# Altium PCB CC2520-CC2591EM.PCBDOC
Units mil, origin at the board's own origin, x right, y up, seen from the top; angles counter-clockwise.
Board outline 1549 x 1978 mil, 4 copper layers (1, AGND, 3, 4); 56 components, 48 nets, 225 pads, 432 vias.
Unrouted connection lines stored in the file: 5.
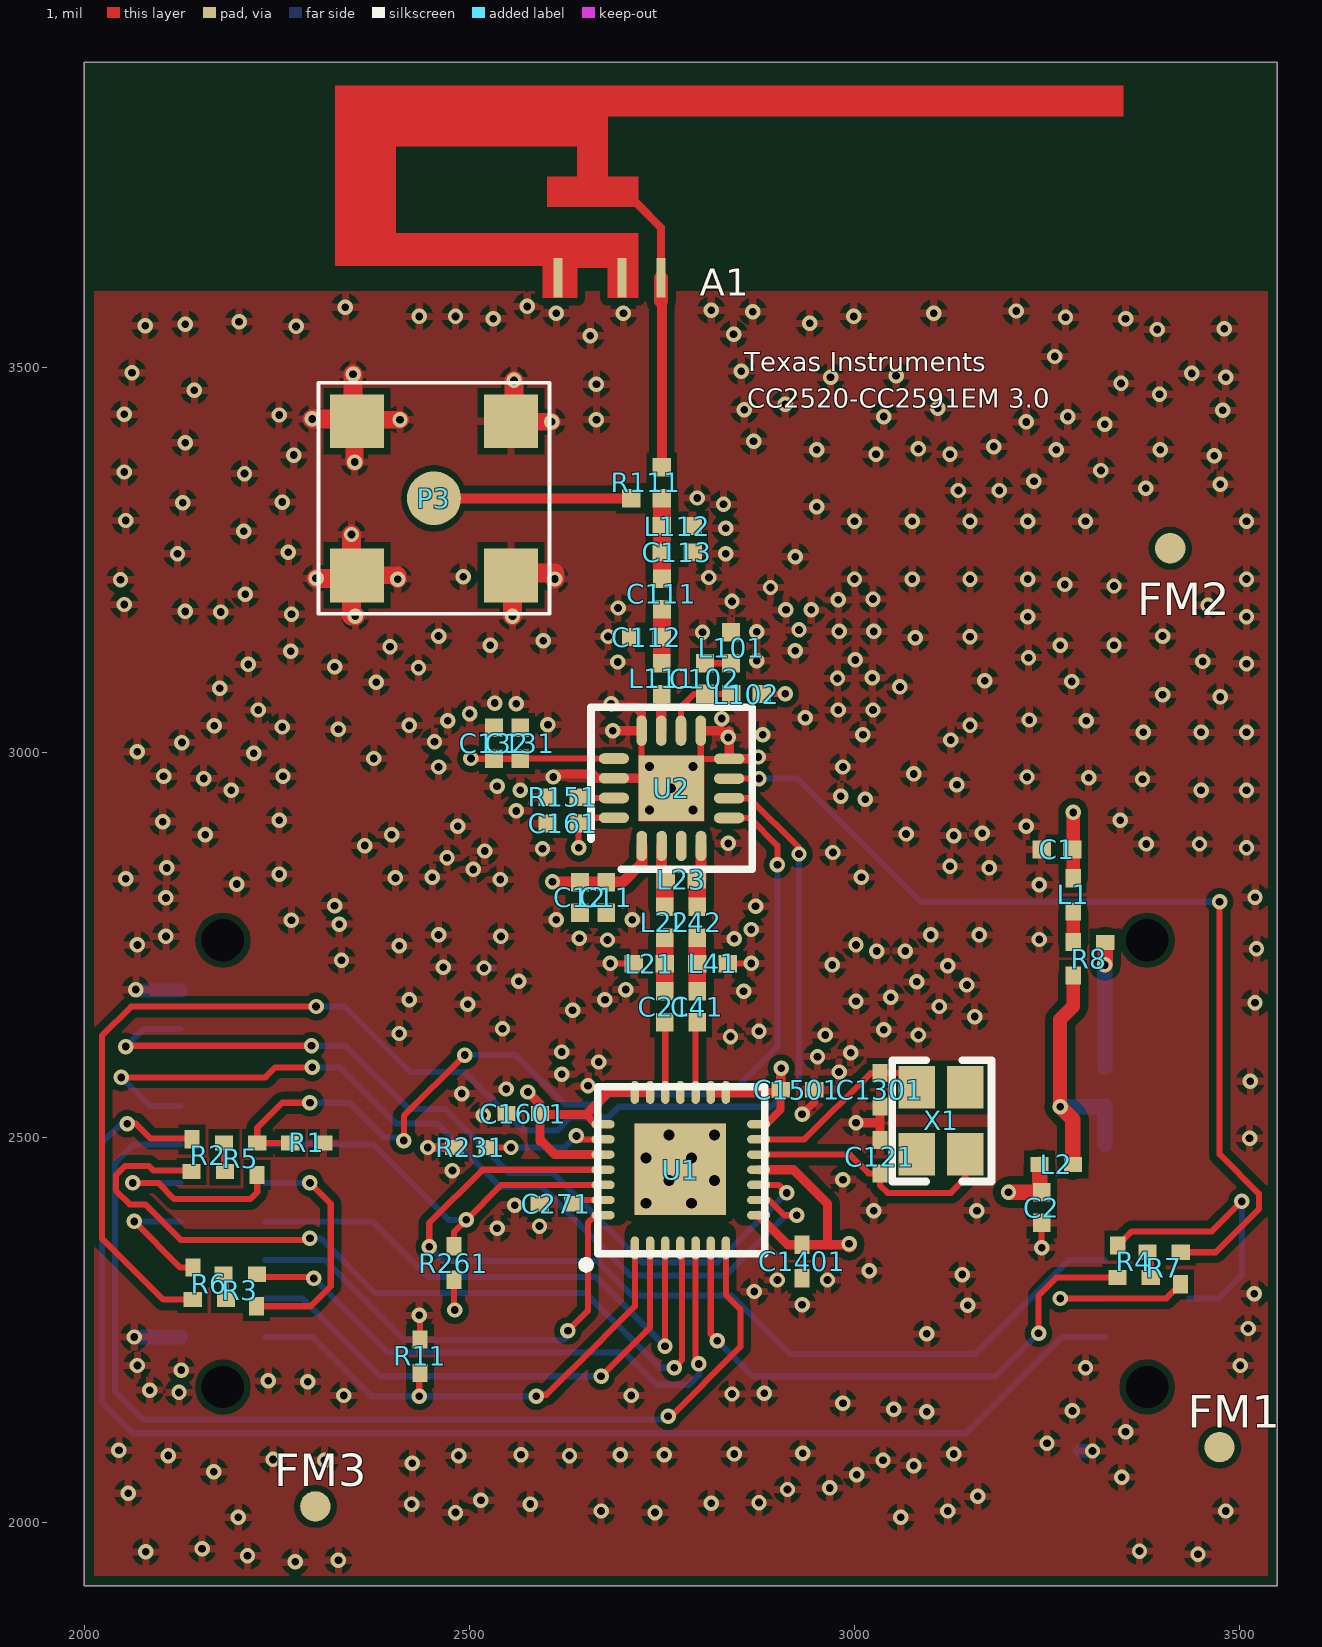
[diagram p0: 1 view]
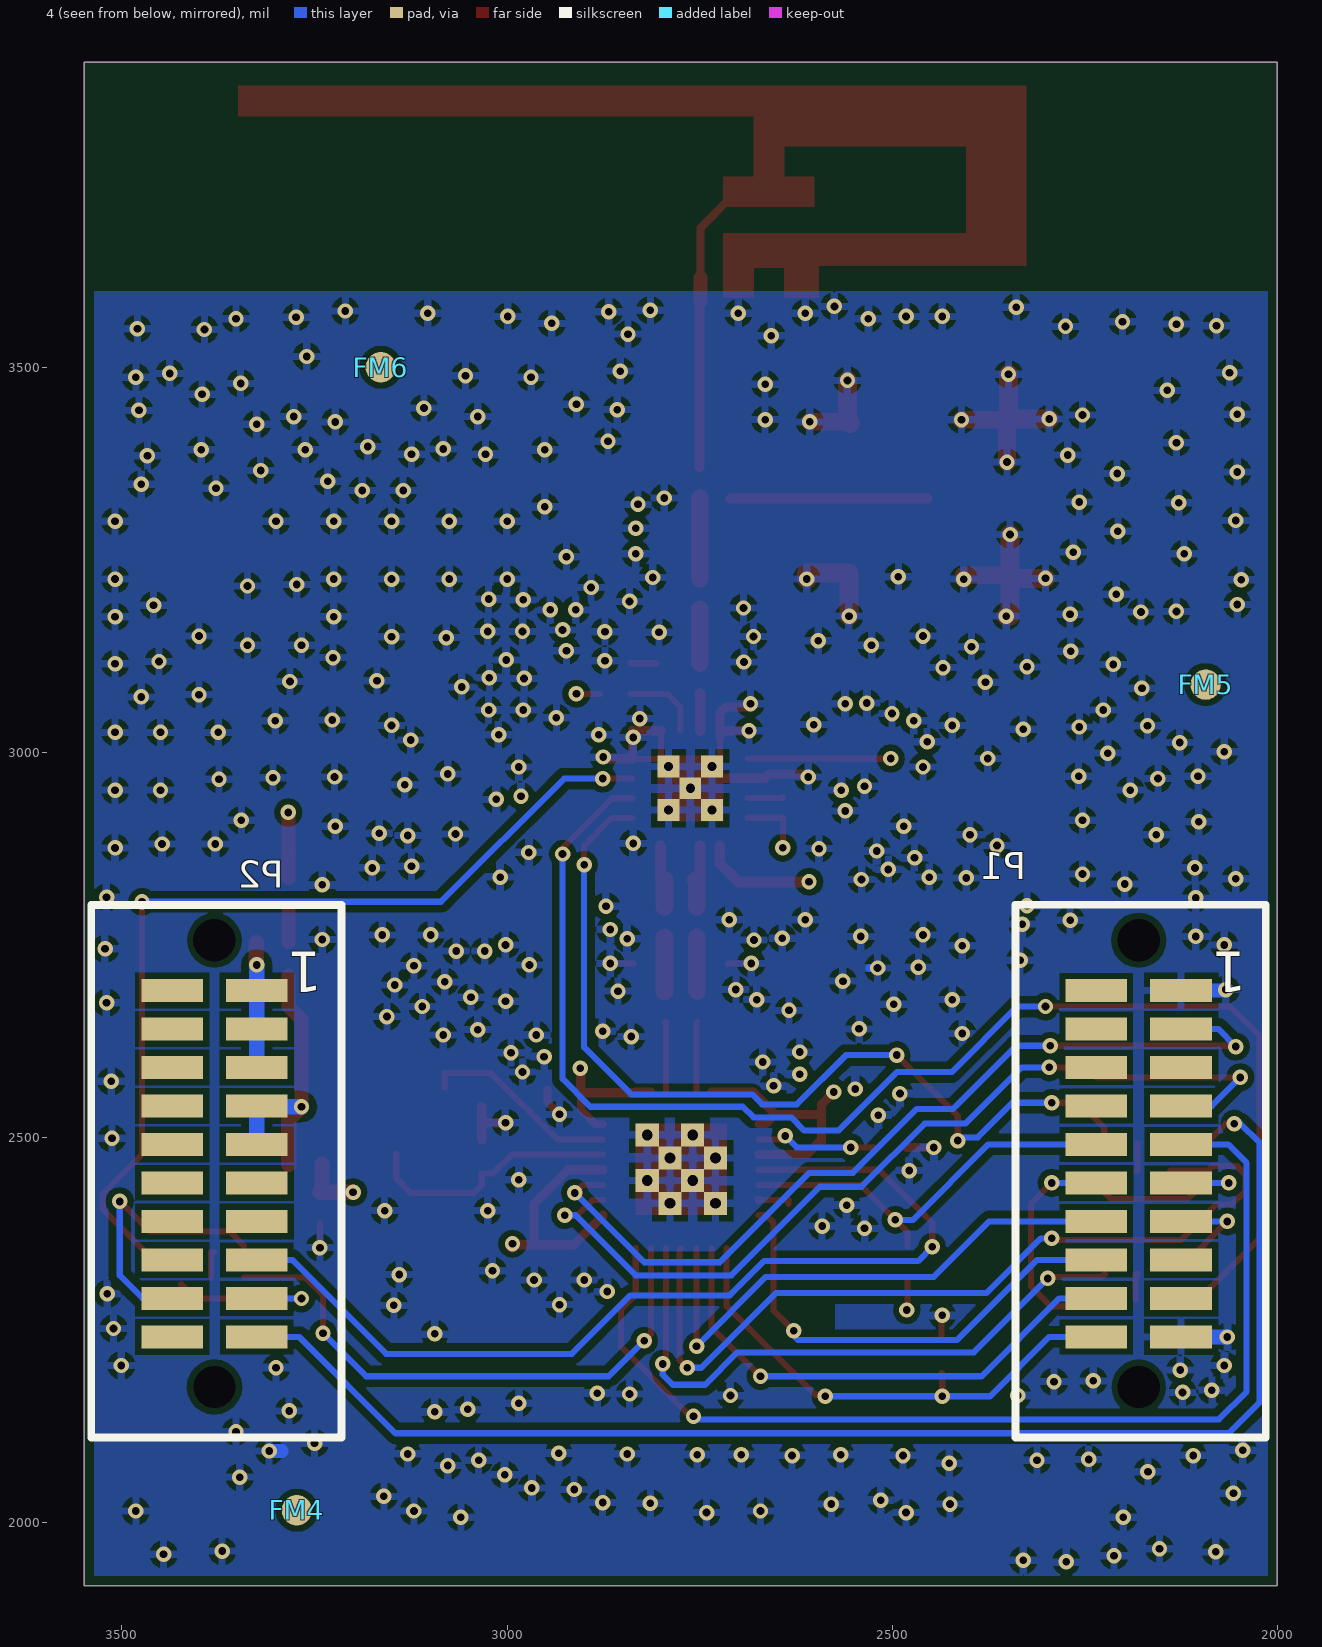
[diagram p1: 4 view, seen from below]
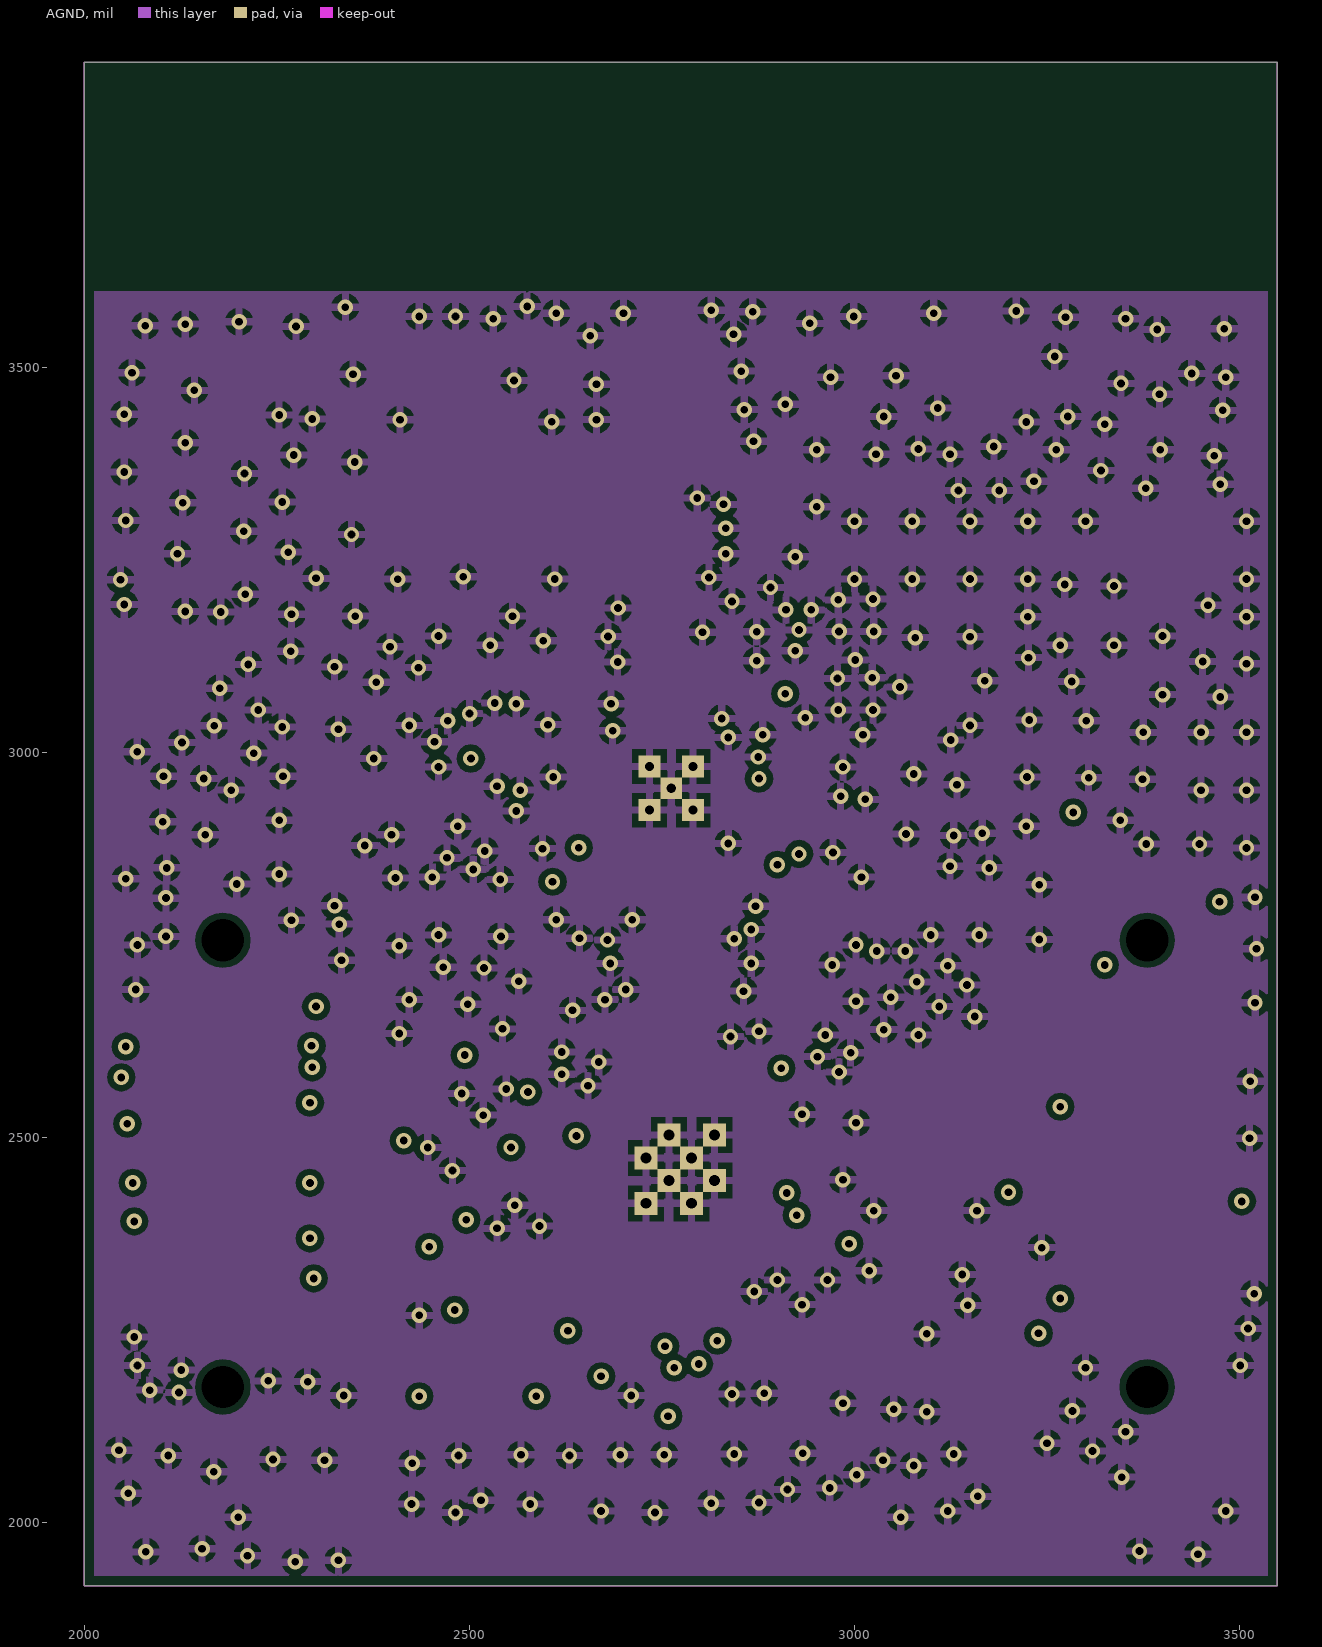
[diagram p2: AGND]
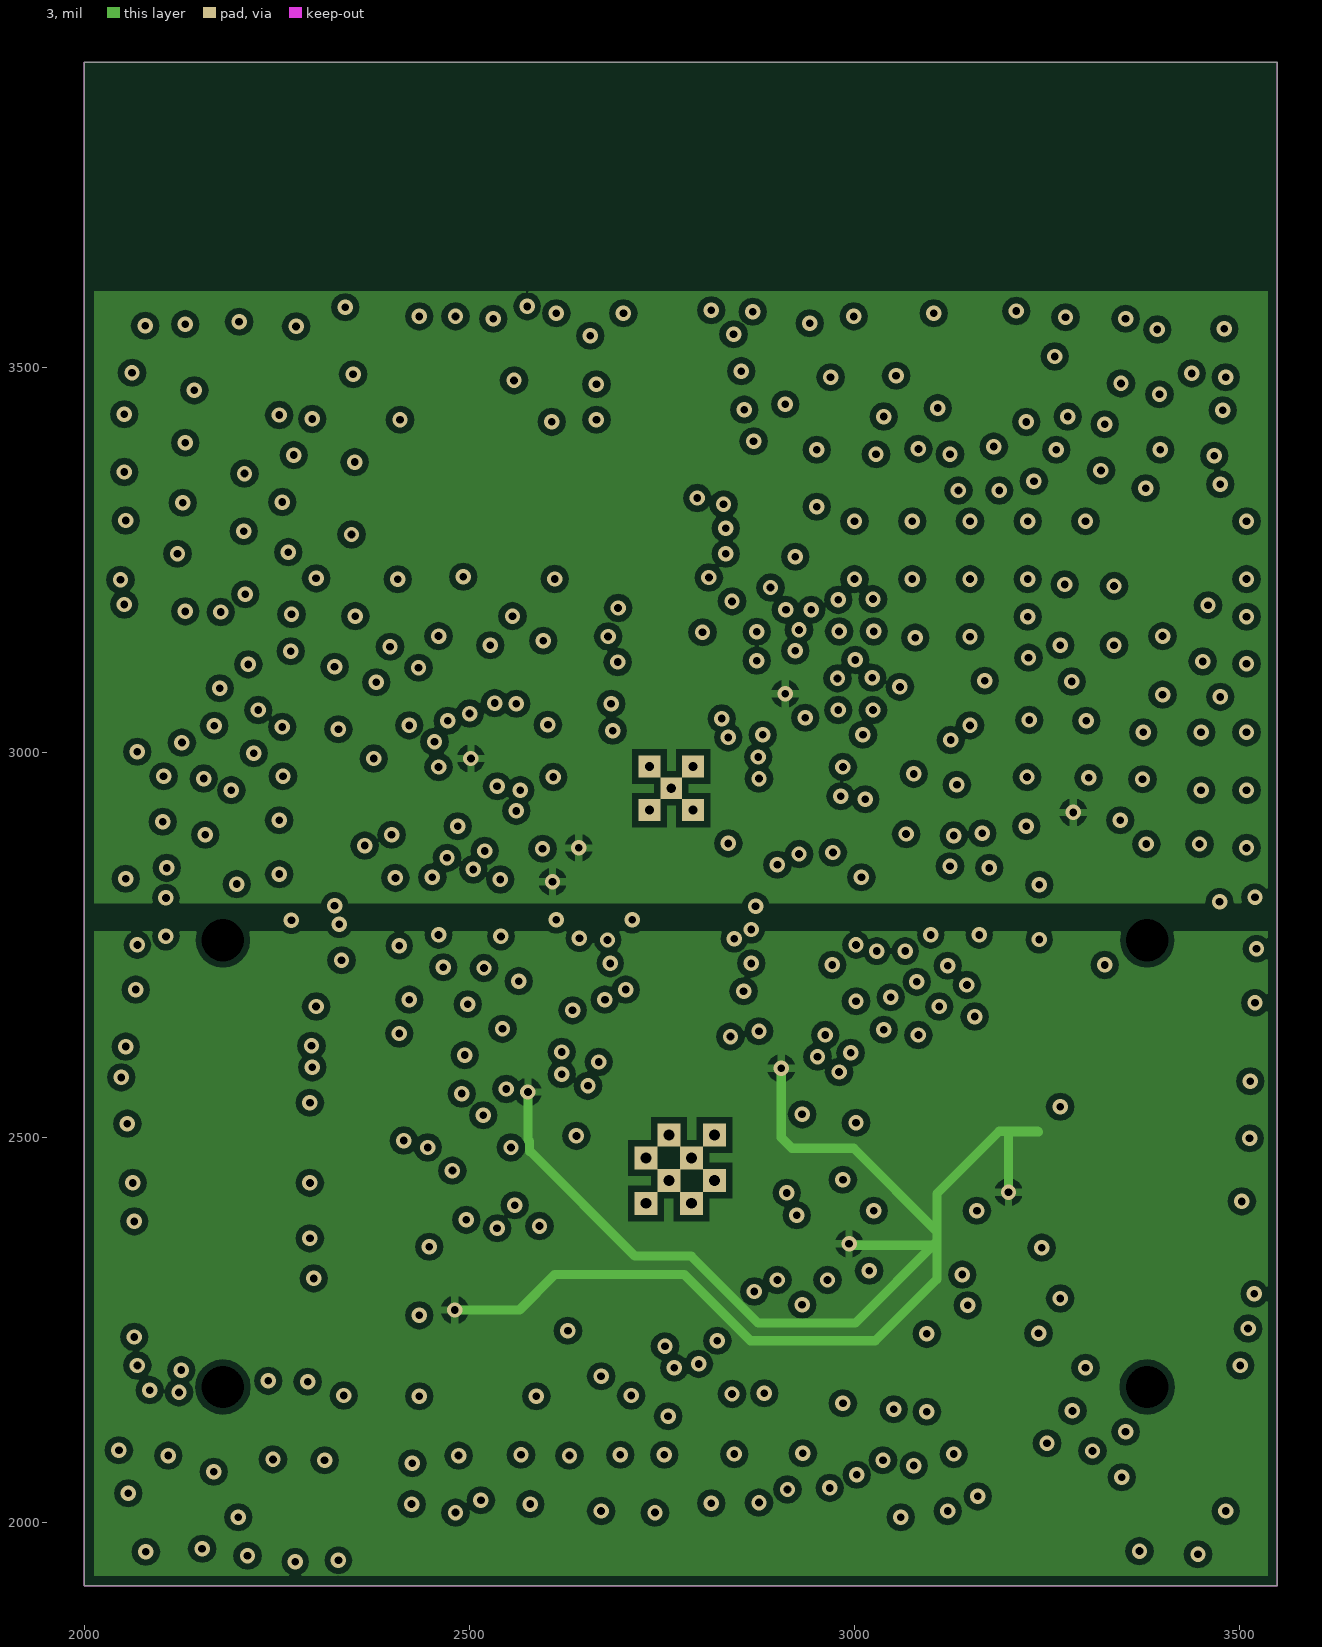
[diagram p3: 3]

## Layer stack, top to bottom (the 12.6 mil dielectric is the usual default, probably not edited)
1: signal copper (thickness not stored)
Dielectric: dielectric 12.6, FR-4, Dk 4.8
AGND: signal copper (thickness not stored)
Dielectric: dielectric 12.6, FR-4, Dk 4.8
3: signal copper (thickness not stored)
Dielectric: dielectric 12.6, FR-4, Dk 4.8
4: signal copper (thickness not stored)

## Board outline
2000,1918 3549,1918 3549,3896 2000,3896

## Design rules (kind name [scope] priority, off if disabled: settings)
Clearance InPolygon_VDD_CC2520_L3_2 [InNamedPolygon('VDD_CC2520_L3_2') vs InNet('VDD_CC2520')] p1: gap=8
Clearance InPolygon_AGND_L1_2 [InNamedPolygon('AGND_L1_2') vs InNet('AGND')] p2: gap=8
Clearance InPolygon_AGND_L4_6 [InNamedPolygon('AGND_L4_6') vs InNet('AGND')] p3: gap=8
Clearance InPolygon_AGND_L4_4 [InNamedPolygon('AGND_L4_4') vs InNet('AGND')] p4: gap=8
Clearance InPolygon_AGND_L2_2 [InNamedPolygon('AGND_L2_2') vs InNet('AGND')] p5: gap=8
Clearance InPolygon_AGND_L4_5 [InNamedPolygon('AGND_L4_5') vs InNet('AGND')] p6: gap=8
Clearance InPolygon_AGND_L4_1 [InNamedPolygon('AGND_L4_1') vs InNet('AGND')] p7: gap=8
Clearance InPolygon_AGND_L4_3 [InNamedPolygon('AGND_L4_3') vs InNet('AGND')] p8: gap=8
Clearance InPolygon_AGND_L2_1 [InNamedPolygon('AGND_L2_1') vs InNet('AGND')] p9: gap=8
Clearance InPolygon_AGND_L4_2 [InNamedPolygon('AGND_L4_2') vs InNet('AGND')] p10: gap=8
Clearance InPolygon_VDD_CC2590_L3_1 [InNamedPolygon('VDD_CC2590_L3_1') vs InNet('VDD_CC2591')] p11: gap=8
Clearance InPolygon_AGND_L1_1 [InNamedPolygon('AGND_L1_1') vs InNet('AGND')] p12: gap=8
Clearance CopperToBoard [InPolygon vs (IsTrack Or IsArc) And OnLayer('Keep-out Layer')] p13: gap=12
Clearance ViaToCopper [IsVia vs InPolygon] p14: gap=8
Clearance ViaToVia [IsVia vs IsVia] p15: gap=8
Clearance PadToCopper [IsPad vs InPolygon] p16: gap=8
Clearance PadToVia [IsPad vs IsVia] p17: gap=8
Clearance PadToPad [IsPad vs IsPad] p18: gap=8
Clearance RouteToPad_1 [IsTrack or IsArc vs IsVia] p19: gap=8
Clearance RouteToPad [IsTrack Or IsArc vs IsPad] p20: gap=8
Clearance RouteToRoute [IsTrack or IsArc vs IsTrack or IsArc] p21: gap=8
Clearance [All] p22: gap=10
PolygonConnect [All] p1: connectstyle=Relief reliefconductorwidth=10 reliefentries=4 polygonreliefangle="90 Angle"
RoutingVias [All] p1: holewidth=28 width=50 viastyle="Through Hole" minholewidth=28 minwidth=50 maxholewidth=28 maxwidth=50
SilkscreenOverComponentPads [All] p1: minsilkscreentomaskgap=10
SolderMaskExpansion [All] p1: expansion=4
Width [All] p1: maxlimit=10 minlimit=10 preferedwidth=10
27 further rules are at their usual default settings.

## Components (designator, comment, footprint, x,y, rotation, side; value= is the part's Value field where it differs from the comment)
A1 "Comment" antenna_IIFA_cc2420 2799,3593 r0 top
C1 "Comment" "0402 (REFLOW LF)" 3263,2874 r180 top
C2 "Comment" "0402 (REFLOW LF)" 3243,2409 r270 top
C11 "Comment" "0402 (REFLOW LF)" 2677.8,2811.6 r270 top
C12 "Comment" "0402 (REFLOW LF)" 2643.7,2811.6 r270 top
C21 "Comment" "0402 (REFLOW LF)" 2753.5,2669.7 r90 top
C41 "Comment" "0402 (REFLOW LF)" 2795.7,2669.6 r90 top
C102 "Comment" "0402 (REFLOW LF)" 2805.8,3095.8 r90 top
C111 "Comment" "0402 (REFLOW LF)" 2750,3205.7 r90 top
C112 "Comment" "0402 (REFLOW LF)" 2730,3149.7 r180 top
C113 "Comment" "0402 (REFLOW LF)" 2770,3259.8 r180 top
C121 "Comment" "0402 (REFLOW)" 3033,2475 r90 top
C131 "Comment" "0402 (REFLOW LF)" 2566,3011.7 r90 top
C132 "Comment" "0402 (REFLOW LF)" 2532,3011.7 r90 top
C161 "Comment" "0402 (REFLOW LF)" 2621.8,2907.7 r180 top
C271 "Comment" "0402 (REFLOW)" 2613,2414 r180 top
C1301 "Comment" "0402 (REFLOW)" 3033,2562 r270 top
C1401 "Comment" "0402 (REFLOW)" 2932,2339 r270 top
C1501 "Comment" "0402 (REFLOW)" 2926,2562 r0 top
C1601 "Comment" "0402 (REFLOW)" 2570,2531 r180 top
FM1 "Comment" FIDUCAL_MARK_1mm 3474,2098 r0 top
FM2 "Comment" FIDUCAL_MARK_1mm 3410,3265 r90 top
FM3 "Comment" FIDUCAL_MARK_1mm 2300,2021 r0 top
FM4 "Comment" FIDUCAL_MARK_1mm 3273,2016 r180 bottom
FM5 "Comment" FIDUCAL_MARK_1mm 2093,3088 r180 bottom
FM6 "Comment" FIDUCAL_MARK_1mm 3164,3500 r180 bottom
L1 "Comment" "0402 (REFLOW)" 3284,2815 r270 top
L2 "Comment" "0402 (REFLOW)" 3262,2465 r0 top
L21 "Comment" "0402 (REFLOW LF)" 2733.7,2725.6 r180 top
L22 "Comment" "0402 (REFLOW LF)" 2753.7,2779.5 r90 top
L23 "Comment" "0402 (REFLOW LF)" 2775,2834.6 r0 top
L41 "Comment" "0402 (REFLOW LF)" 2815.7,2725.6 r0 top
L42 "Comment" "0402 (REFLOW LF)" 2795.7,2779.6 r90 top
L101 "Comment" "0402 (REFLOW LF)" 2839.8,3135.8 r90 top
L102 "Comment" "0402 (REFLOW LF)" 2859.75,3075.75 r180 top
L111 "Comment" "0402 (REFLOW LF)" 2749.75,3095.75 r90 top
L112 "Comment" "0402 (REFLOW LF)" 2770,3293.8 r180 top
P1 "Comment" "SFM SMD Socket 2x10" 2125,2691 r0 bottom
P2 "Comment" "SFM SMD Socket 2x10" 3325,2690.95 r0 bottom
P3 "Comment" "SMA_SMD (Straight)" 2454,3329.9 r0 top
R1 "Comment" "0402 (REFLOW)" 2289,2493 r180 top
R2 "Comment" "0402_3port_1-2 (REFLOW)" 2161,2456 r180 top
R3 "Comment" "0402_3port_1-2 (REFLOW)" 2202.5,2322.5 r0 top
R4 "Comment" "0402_3port_1-2 (REFLOW)" 3363,2318 r180 top
R5 "Comment" "0402_3port_1-2 (REFLOW)" 2203,2493 r0 top
R6 "Comment" "0402_3port_1-2 (REFLOW)" 2162.5,2289.5 r180 top
R7 "Comment" "0402_3port_1-2 (REFLOW)" 3402,2351 r0 top
R8 "Comment" "0402_3port_1-2 (REFLOW)" 3284,2732 r90 top
R11 "Comment" "0402 (REFLOW)" 2436,2216 r90 top
R111 "Comment" "0402_3port_2-3 (REFLOW LF)" 2729.8,3329.8 r270 top
R151 "Comment" "0402 (REFLOW LF)" 2621.8,2941.7 r0 top
R231 "Comment" "0402 (REFLOW)" 2502,2487 r0 top
R261 "Comment" "0402 (REFLOW)" 2480,2337 r270 top
U1 "Comment" "QLP28 (Reflow)" 2774,2457 r90 top
U2 "Comment" "QFN16_4_4_DATASHEET (CC2591)" 2759,2966 r90 top
X1 "Comment" "XTAL_SMD_3_2x2_5 (3.2 x 2.5 mm)" 3081,2565 r270 top

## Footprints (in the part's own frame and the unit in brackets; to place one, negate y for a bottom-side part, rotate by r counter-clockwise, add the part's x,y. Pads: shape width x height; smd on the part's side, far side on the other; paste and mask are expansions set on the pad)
"0402 (REFLOW LF)" [mil]
  rect 24x23 smd paste+0 mask+6: 1(-20,0) 2(20,0)
"0402 (REFLOW)" [mm]
  rect 0.6x0.5 smd paste+0 mask+0.1: 1(-0.55,0) 2(0.55,0)
"0402_3port_1-2 (REFLOW)" [mm]
  rect 0.6x0.5 smd paste+0 mask+0.1: 1(-0.55,0) 2(0.55,0)
  rect 0.5x0.6 smd paste+0 mask+0.1: 3(0.537,-1.057)
"0402_3port_2-3 (REFLOW LF)" [mil]
  rect 24x24 smd paste+0 mask+6: 1(-40.1,20.1) 2(-0.1,20.1) 3(-0.1,-19.9)
antenna_IIFA_cc2420 [mm]
  rect 0.3x1.3 smd paste-0.3 mask-0.3: 1(-1.27,0.584) 2(-2.565,0.584) 3(-4.674,0.584)
  1 region: -1.397,2.134 -1.422,2.21 -2.261,3.048 -2.032,3.175 -1.143,2.286 -1.143,2.134
  1 region: -1.143,-0.076 -1.397,-0.076 -1.397,2.147 -1.143,2.147
  1 region: -2.03,-0.076 -3.03,-0.076 -3.03,0.924 -4.03,0.924 -4.03,-0.076 -5.18,-0.076 -5.18,0.991 -12.012,0.991 -12.012,6.924 13.97,6.924 13.97,5.924 -3.03,5.924 -3.03,3.924 -2.03,3.924 -2.03,2.924 -5.03,2.924 -5.03,3.924 -4.03,3.924 -4.03,4.924 -10.03,4.924 -10.03,2.057 -2.03,2.057
FIDUCAL_MARK_1mm [mil]
  round 39.4 smd paste+0 mask+39.4: 1(0,0)
"QFN16_4_4_DATASHEET (CC2591)" [mm]
  oval 1x0.35 smd paste+0.001 mask+0.14: 1(-2.22,0.89) 2(-2.22,0.24) 3(-2.22,-0.41) 4(-2.22,-1.06) 9(1.58,-1.05) 10(1.58,-0.4) 11(1.58,0.25) 12(1.58,0.9)
  oval 0.35x1 smd paste+0.001 mask+0.14: 5(-1.3,-1.99) 6(-0.65,-1.99) 7(0,-1.99) 8(0.65,-1.99) 13(0.66,1.81) 14(0.01,1.81) 15(-0.64,1.81) 16(-1.29,1.81)
  rect 0.72x0.72 hole 0.3 paste+0 mask+0.14: 17(-1.04,0.64) 19(0.4,0.64) 21(-0.32,-0.08) 23(-1.04,-0.8) 25(0.4,-0.8)
  rect 0.72x0.72 smd paste-0.72 mask+0.14: 18(-0.32,0.64) 20(-1.04,-0.08) 22(0.4,-0.08) 24(-0.32,-0.8)
  1 region: -1.4,-1.16 0.76,-1.16 0.76,1 -1.4,1
  1 region: -1.4,-1.16 0.76,-1.16 0.76,1 -1.4,1
  1 region: -1.4,-1.16 0.76,-1.16 0.76,1 -1.4,1
  1 region: -1.4,-1.16 0.76,-1.16 0.76,1 -1.4,1
  1 region: -1.4,-1.16 0.76,-1.16 0.76,1 -1.4,1
  1 region: -1.4,-1.16 0.76,-1.16 0.76,1 -1.4,1
  1 region: -1.4,-1.16 0.76,-1.16 0.76,1 -1.4,1
  1 region: -1.4,-1.16 0.76,-1.16 0.76,1 -1.4,1
  silkscreen extent -2.99,-2.75 2.35,2.57
"QLP28 (Reflow)" [mil]
  oval 30x11 smd paste+0 mask+2: 1(-100.39,59.06) 2(-100.39,39.37) 3(-100.39,19.68) 4(-100.39,0) 5(-100.39,-19.69) 6(-100.39,-39.37) 7(-100.39,-59.06) 15(101.57,-59.06) 16(101.57,-39.37) 17(101.57,-19.69) 18(101.57,0) 19(101.57,19.68) 20(101.57,39.37) 21(101.57,59.06)
  oval 11x30 smd paste+0 mask+2: 8(-57.87,-101.57) 9(-38.19,-101.57) 10(-18.5,-101.57) 11(1.18,-101.57) 12(20.87,-101.57) 13(40.55,-101.57) 14(60.24,-101.57) 22(60.24,100.39) 23(40.55,100.39) 24(20.87,100.39) 25(1.18,100.39) 26(-18.5,100.39) 27(-38.19,100.39) 28(-57.87,100.39)
  rect 30x30 hole 14 paste+0 mask+0: 29(-42.52,44.49) 31(16.54,44.49) 34(-12.99,14.96) 36(46.06,14.96) 37(-42.52,-14.57) 39(16.54,-14.57) 42(-12.99,-44.09) 44(46.06,-44.09)
  rect 30x30 smd mask+0: 30(-12.99,44.49) 32(46.06,44.49) 33(-42.52,14.96) 35(16.54,14.96) 38(-12.99,-14.57) 40(46.06,-14.57) 41(-42.52,-44.09) 43(16.54,-44.09)
  1 region: -55.51,57.48 59.06,57.48 59.06,-57.09 -55.51,-57.09
  1 region: -55.51,57.48 59.06,57.48 59.06,-57.09 -55.51,-57.09
  1 region: -55.51,57.48 59.06,57.48 59.06,-57.09 -55.51,-57.09
  1 region: -55.51,57.48 59.06,57.48 59.06,-57.09 -55.51,-57.09
  1 region: -55.51,57.48 59.06,57.48 59.06,-57.09 -55.51,-57.09
  1 region: -55.51,57.48 59.06,57.48 59.06,-57.09 -55.51,-57.09
  1 region: -55.51,57.48 59.06,57.48 59.06,-57.09 -55.51,-57.09
  1 region: -55.51,57.48 59.06,57.48 59.06,-57.09 -55.51,-57.09
  1 region: -55.51,57.48 59.06,57.48 59.06,-57.09 -55.51,-57.09
  1 region: -55.51,57.48 59.06,57.48 59.06,-57.09 -55.51,-57.09
  1 region: -57.48,59.45 61.02,59.45 61.02,-59.06 -57.48,-59.06
  1 region: -55.51,57.48 59.06,57.48 59.06,-57.09 -55.51,-57.09
  1 region: -55.51,57.48 59.06,57.48 59.06,-57.09 -55.51,-57.09
  1 region: -55.51,57.48 59.06,57.48 59.06,-57.09 -55.51,-57.09
  1 region: -55.51,57.48 59.06,57.48 59.06,-57.09 -55.51,-57.09
  silkscreen extent -132,-109 109,132
"SFM SMD Socket 2x10" [mil]
  rect 80x30 smd paste-2 mask+4: 1(0,0) 2(110,0) 3(0,50) 4(110,50) 5(0,100) 6(110,100) 7(0,150) 8(110,150) 9(0,200) 10(110,200) 11(0,250) 12(110,250) 13(0,300) 14(110,300) 15(0,350) 16(110,350) 17(0,400) 18(110,400) 19(0,450) 20(110,450)
  round 5 hole 55 paste+0 mask+55: 21(55,-65) 22(54.96,515)
  silkscreen extent -110,-111 215,581
"SMA_SMD (Straight)" [mil]
  round 70 smd paste+0 mask+3: 1(0,0)
  rect 70x70 smd paste+0 mask+3: 2(-100,100) 3(-100,-100) 4(100,-100) 5(100,100)
  silkscreen extent -150,-150 150,150
"XTAL_SMD_3_2x2_5 (3.2 x 2.5 mm)" [mm]
  rect 1.4x1.2 smd paste-0.001 mask+0.05: 1(0,0) 2(2.2,0) 3(2.2,1.6) 4(0,1.6)
  silkscreen extent -0.9,-0.81 3.1,2.46

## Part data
A1: library part Antenna_IIFA_cc2420, "Antenna single ended IIFA, CC2420"
C1 C2: library part C_2U2_0402_X5R_M_4VDC, "Capasitor 0402, GRM155R60G225ME15J"
C11 C131 C161: library part C_1N_0402_NP0_J_50, "Capacitor 0402"
C12 C132: library part C_0402, "Capacitor 0402, general"
C21: library part C_3P0_0402_NP0_C_50, "Capacitor 0603"
C41: library part C_3P9_0402_NP0_C_50, "Capacitor 0402"
C102: library part L_1N1_0402_S, "Inductor, 1n1, 0402, LQG15HS1N1S02D"
C111: library part C_6P8_0402_NP0_C_50, "Capacitor 0402"
C112: library part C_1P0_0402_NP0_B_50, "Capacitor, 1p, 0402, NP0, +/-0.1pF 50V"
C113: library part C_2P7_0402_NP0_C_50, "Capacitor 0402"
C121 C1301: library part C_27P_0402_NP0_J_50, "Capacitor 0402"
C271 C1401 C1501 C1601: library part C_100N_0402_X5R_K_10, "Capacitor 0402"
FM1 FM2 FM3 FM4 FM5 FM6: library part FIDUCIAL_MARK_1MM, "Fiducial mark, 1mm metal diameter"
L1 L2: library part L_BEAD_102_0402, "EMI filter bead"
L21 L41 L42 L112: library part L_1N0_0402_S, "Inductor 0402"
L22: library part L_2N0_0402_S, "Inductor 0402"
L23: library part L_0402, "Inductor 0402, general"
L101: library part C_15P_0402_NP0_J_50, "Capacitor, 0402"
L102: library part L_5N1_0402_J, "Inductor 0402"
L111: library part L_1N5_0402_B_LQW, "Inductor, 1n5, 0402, Wire-wound type, +/-0.1 nH"
P1 P2: library part SMD_SOCKET_2x10, "SMD pinrow socket, .050 spacing, SFM-110-02-SM-D-A-K-TR"
P3: library part SMA_SMD, "Surface-mount SMA, straight"
R1: library part R_330K_0402_F, "Resistor 0402"
R2 R3 R4 R5 R6 R7 R8: library part R_0_0402_3PORT_1-2, "0402 3-port footprint, default connection 1-2"
R11: library part R_1M0_0402_F, "Resistor 0402"
R111: library part R_0_0402_3PORT_2-3, "0402 3-port footprint, default connection 2-3"
R151: library part R_4K3_0402_G, "Resistor 0402"
R231: library part R_56K_0402_F, "Resistor 0402"
R261: library part R_0402, "Resistor 0402, general"
U1: library part CC2520, "Single-chip transceiver"
U2: library part CC2591_DATASHEET, "CC2591 w/ datasheet footprint"
X1: library part X_32.000/10/15/30/16, "Crystal, ceramic SMD 3.2x2.5mm"

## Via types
v1: diameter 20, hole 10, 1 to 4, 432 vias

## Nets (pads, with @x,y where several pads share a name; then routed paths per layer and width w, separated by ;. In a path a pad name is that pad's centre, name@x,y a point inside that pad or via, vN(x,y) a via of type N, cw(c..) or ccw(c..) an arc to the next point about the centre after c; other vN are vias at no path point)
276: C1301.1 U1.13 X1.1 | length 270.7
  1 w8: U1.13 2934.9,2497.55 3021,2583.65 C1301.1 ; C1301.1 C1301.1@3038,2583.65 ; C1301.1 C1301.1@3038,2583.65 ; C1301.1@3038,2583.65 3081,2583.65 X1.1@3081,2571 ; X1.1@3081,2571 X1.1 X1.1@3081,2571
528: P2.15 U1.25 | length 1395.8
  1 w8: v1(2448,2358) 2448,2389 2517.18,2458.18 2548.18,2458.18 ; 2548.18,2458.18 U1.25 2548.18,2458.18
  4 w8: v1(2448,2358) 2466.5,2339.5 2666.5,2339.5 2711,2295 2840,2295 2916,2219 3157.05,2219 3279,2340.95 P2.15
536: R231.2 U1.23 | length 160.6
  1 w8: R231.2 v1(2554,2487) ; v1(2639,2502) 2639,2497.55 U1.23
  4 w8: v1(2554,2487) 2624,2487 v1(2639,2502)
571: C271.1 U1.27 | length 83.1
  1 w8: C271.1 2634.65,2418.81 U1.27 2673.61,2419 C271.1@2634.65,2419
  1 w10: U1.27 U1.27@2673.61,2419
574: P1.10 R261.1 U1.26 | length 548.5
  1 w8: R261.1 2480,2377 v1@2495,2392 ; v1(2496,2393) v1@2495,2392 ; U1.26@2665.5,2438.5 U1.26 2541.5,2438.5 v1@2495,2392
  4 w8: P1.10 2375,2491 2473,2393 v1(2496,2393)
576: P1.20 R11.1 U1.1 | length 676
  1 w8: v1(2435,2164) 2435,2193.5 R11.1 ; v1(2587,2164) 2587,2166 2600,2166 2629,2195 ; U1.1 2714.94,2280.94 2634,2200 ; 2629,2195 2634,2200 ; 2629,2195 2634,2200
  4 w8: P1.20 2296,2241 2373,2164 v1@2436,2164 ; v1(2435,2164) v1@2436,2164 ; v1(2587,2164) v1@2436,2164
577: P1.18 U1.2 | length 672
  1 w8: v1(2671,2190) 2673,2190 2673,2192 2734.63,2253.63 2734.63,2270.63 U1.2
  4 w8: P1.18 2283,2291 2384,2190 v1(2671,2190)
578: P1.16 U1.28 | length 621.6
  1 w8: v1(2628,2249) 2654,2275 2654,2389 2664.13,2399.13 U1.28
  4 w8: P1.16 2312,2341 2416,2237 2622,2237 2630,2245 2627,2248 v1(2628,2249)
579: P1.14 U1.3 | length 714.3
  1 w8: v1(2754,2229) U1.3@2754,2356.61 ; U1.3@2754,2356.61 U1.3 U1.3@2754,2356.61
  4 w8: P1.14 2374,2391 2446,2319 2664,2319 v1(2754,2229)
588: P1.3 U1.10 | length 1151.3
  1 w8: v1(2054,2618) 2054,2619 v1(2295,2619) ; U1.10@2883.86,2438.5 U1.10 2901.5,2438.5 v1@2911,2429 ; v1@2905,2435 v1@2911,2429 ; v1(2912,2428) v1@2911,2429
  4 w8: v1(2054,2618) 2077,2641 P1.3 ; v1(2295,2619) 2340,2619 2340,2618 2421,2537 2468,2537 2551,2454 2608,2454 2724,2338 2822,2338 v1(2912,2428)
589: P1.7 U1.9 | length 1176.5
  1 w8: v1(2048,2578) 2235,2578 2248,2591 v1(2296,2591) ; U1.9 2889.19,2418.81 2909,2399 v1(2925,2399)
  4 w8: v1(2048,2578) 2085,2541 P1.7 ; v1(2296,2591) 2332,2591 2405,2518 2458,2518 2540,2436 2594,2436 2709,2321 2833,2321 2911,2399 v1(2925,2399)
604: C121.1 U1.12 X1.3 | length 337.3
  1 w8: U1.12 2994,2477.87 3018.52,2453.35 C121.1 3033,2438 3043,2428 3125,2428 3143.99,2446.99 X1.3
632: R151.2 U2.15 | length 46.8
  1 w8: R151.2 2641.8,2940.8 U2.15
661: P1.12 R3.3 | length 310.4
  1 w8: R3.3 2294,2280.9 2320,2306.9 2320,2414 v1(2293,2441)
  4 w8: P1.12 v1(2293,2441)
664: P2.18 R4.3 | length 361.4
  1 w8: R4.3 3360.25,2378 3464,2378 v1(3503,2417)
  4 w8: P2.18 3472.95,2290.95 3503,2321 v1(3503,2417)
670: R6.2 U2.6 | length 1848.3
  1 w8: 2023,2531 2023,2529 ; R6.2 2102.5,2289.5 2023,2369 2023,2529 ; v1(2301,2670) 2061,2670 2023,2632 2023,2529 ; U2.6 2863.59,2940.41 2928,2876 v1(2928,2868)
  4 w8: v1(2301,2670) 2338,2670 2423,2585 2494,2585 2570,2509 2614,2509 2631,2526 2680,2526 2694,2540 2892,2540 2928,2576 v1(2928,2868)
672: P1.11 R5.3 | length 259.5
  1 w8: v1(2063,2441) 2096,2441 2117,2420 2215.65,2420 2224.65,2429 R5.3@2224.65,2451.4 ; R5.3@2224.65,2451.4 R5.3 R5.3@2224.65,2451.4
  4 w8: v1(2063,2441) P1.11
673: P1.13 R6.3 | length 161.2
  1 w8: v1(2065,2391) 2124.9,2331.1 R6.3
  4 w8: v1(2065,2391) P1.13
674: P2.17 R7.3 | length 221.8
  1 w8: v1(3267,2291) 3404.75,2291 R7.3
  4 w8: v1(3267,2291) P2.17
675: R7.2 U2.7 | length 1259.6
  1 w8: U2.7 2864,2966 ; R7.2 3469,2351 3525,2407 3525,2427 3474,2478 v1(3474,2806) ; 2864,2966 v1(2876,2966) 2864,2966
  4 w8: v1(2876,2966) 2926,2966 3086,2806 v1(3474,2806)
676: R1.2 R5.2 U2.5 | length 1277.8
  1 w8: v1(2293,2545) 2257,2545 2224.65,2512.65 R5.2 ; v1(2415,2496) 2415,2528 v1(2494,2607) ; U2.5 2864.18,2914.82 2900,2879 v1(2900,2854) ; R5.2 R1.2 R5.2
  4 w8: v1(2293,2545) 2344,2545 2389,2500 2415,2500 v1(2415,2496) ; v1(2494,2607) 2560,2607 2624,2543 2669,2543 2682,2556 2839,2556 2900,2617 v1(2900,2854)
677: R2.2 U1.4 | length 1114.1
  1 w8: v1(2293,2369) 2293,2367 2125,2367 2079,2413 2059,2413 2041,2431 2041,2451 2053,2463 2084,2463 2090,2457 R2.2@2138.35,2457 ; v1(2766,2201) 2776,2211 U1.4@2776,2354.61 ; R2.2@2138.35,2457 R2.2 R2.2@2138.35,2457 ; U1.4@2776,2354.61 U1.4 U1.4@2776,2354.61
  4 w8: v1(2293,2369) 2307,2369 2378,2298 2651,2298 2748,2201 v1(2766,2201)
679: R2.1 R5.1 | length 73.3
  1 w8: R2.1@2181.35,2457.5 R5.1 R2.1@2181.35,2457.5 ; R2.1@2181.35,2457.5 R2.1@2182.75,2456.1 ; R2.1@2182.75,2456.1 R2.1 R2.1@2182.75,2456.1
681: R3.1 R6.1 | length 72.6
  1 w8: R3.1@2184.15,2322.5 R6.1 R3.1@2184.15,2322.5 ; R3.1@2184.15,2322.5 R3.1 R3.1@2184.15,2322.5
682: R4.2 U1.6 | length 744.3
  1 w8: U1.6 2813.37,2244.63 v1(2822,2236) ; v1(3239,2246) 3239,2295 3262,2318 R4.2
  4 w8: v1(2822,2236) 2868,2190 3183,2190 v1(3239,2246)
683: R4.1 R7.1 | length 74.6
  1 w8: R7.1@3384.65,2351 R7.1 R7.1@3384.65,2351 ; R7.1@3384.65,2351 R4.1 R7.1@3384.65,2351
690: C21.2 L21.1 L22.1 | length 70
  1 w23: C21.2 2753.7,2689.7 L21.1 L22.1
709: P2.19 R2.3 | length 1844.8
  1 w8: v1(2056,2518) 2067,2518 2086.4,2498.6 R2.3@2138.85,2498.6 ; R2.3@2138.85,2498.6 R2.3 R2.3@2138.85,2498.6
  4 w8: v1(2056,2518) 2048,2518 2023,2493 2023,2156 2063,2116 3144,2116 3144.52,2115.48 3270,2240.95 P2.19
710: P1.9 U1.7 | length 1399.9
  1 w8: v1(2758,2138) 2758,2134 2852,2228 2852,2277 2833.06,2295.94 U1.7
  4 w8: P1.9 2064,2491 2040,2467 2040,2170 2076,2134 2754,2134 v1(2758,2138)
711: R3.2 U1.5 | length 813.6
  1 w8: v1(2298,2317) 2296,2319 R3.2@2227.65,2319 ; v1(2798,2206) 2793.68,2210.32 U1.5@2793.68,2353 ; R3.2@2227.65,2319 R3.2 R3.2@2227.65,2319 ; U1.5@2793.68,2353 U1.5 U1.5@2793.68,2353
  4 w8: v1(2298,2317) 2394,2221 2701,2221 2743,2179 2785,2179 2798,2192 v1(2798,2206)
724: C111.2 C113.2 L112.2 R111.2 | length 104.3
  1 w23: R111.2 2750,3329.9 L112.2 C113.2 C111.2
726: P3.1 R111.3 | length 255.9
  1 w13: P3.1 R111.3
727: A1.1 R111.1 | length 268.5
  1 w12: A1.1@2749,3608 A1.1@2749.9,3607.1
  1 w13: R111.1 A1.1@2749.9,3607.1
  1 w18: 2749,3586 2749,3608 A1.1
754: L23.2 L42.2 U2.4 | length 84.7
  1 w8: L23.2 L23.2@2795.7,2834.6
  1 w14: L23.2@2795.7,2834.6 2800.73,2834.6 U2.4
  1 w23: L42.2 L23.2@2795.7,2834.6
757: C41.2 L41.1 L42.1 | length 70
  1 w23: C41.2 L41.1 L42.1
764: L1.2 R8.2 | length 39.7
  1 w18: R8.2 L1.2
768: C102.1 L102.2 U2.10 | length 102.7
  1 w8: U2.10 2774.75,3058.75 2791.8,3075.8 C102.1 L102.2 L102.2
769: C102.2 L101.1 | length 34
  1 w8: C102.2 L101.1
772: L111.1 U2.11 | length 48.1
  1 w14: U2.11 2749.16,3075.75 L111.1
775: C111.1 C112.1 L111.2 | length 70.2
  1 w23: L111.2 2749.75,3149.7 C112.1 C111.1
783: L22.2 L23.1 U2.2 | length 84.5
  1 w14: U2.2 2749.55,2834.6 L23.1@2753.7,2834.6
  1 w23: L22.2 2753.7,2834.6 L23.1
784: C21.1 U1.19 | length 91.9
  1 w8: C21.1 2754.32,2649.7 U1.19
785: C41.1 U1.17 | length 93
  1 w8: U1.17 2793.68,2649.6 C41.1
AGND: A1.2 A1.3 C1.2 C2.2 C11.2 C12.2 C112.2 C113.1 C121.2 C131.2 C132.2 C161.2 C271.2 C1301.2 C1401.2 C1501.2 C1601.2 L21.2 L41.2 L101.2 L112.1 P1.1 P1.19 P3.2 P3.3 P3.4 P3.5 R1.1 R11.2 R151.1 R231.1 U1.29 U1.30 U1.31 U1.32 U1.33 U1.34 U1.35 U1.36 U1.37 U1.38 U1.39 U1.40 U1.41 U1.42 U1.43 U1.44 U2.8 U2.9 U2.12 U2.14 U2.17 U2.18 U2.19 U2.20 U2.21 U2.22 U2.23 U2.24 U2.25 | length 1802.5
  1 w8: P3.2@2348,3432.9 P3.2@2349,3431.9 ; R11.2 v1@2436,2269 ; P3.5@2554,3429.1 P3.5 ; v1(2683,2726) 2713.7,2726 L21.2 ; U2.14@2705,2966.39 2733.8,2966.39 2733.8,2966 U2.18 ; U2.12@2723.57,3019 2723.57,2991.98 U2.19 ; U2.25 2800.34,2981.75 U2.25@2800.34,2990 ; L41.2 2835.7,2726 v1(2866,2726) ; v1(2932,2530) 2947.65,2545.65 C1501.2 ; v1@3238,2358 v1@3243,2358 ; v1(3243,2357) v1@3243,2358 ; C2.2 v1@3243,2358 ; U2.25@2800.34,2990 U2.9 U2.25@2800.34,2991.59 ; U2.25@2800.34,2990 U2.25@2800.34,2991.59 ; U2.25@2800.34,2991.59 U2.8 U2.25@2800.34,2991.59
  1 w10: U2.14 U2.14@2705,2966.39 ; U2.12@2723.57,3019 2723.57,3022 2723.57,3028 U2.12 ; U2.18 U2.18@2733.8,2966 ; v1(2932,2530) 2947.65,2545.65 C1501.2
  1 w12: v1@2409,3429.9 v1@2410.5,3431.4 ; v1@2445,2487 v1(2446,2487) R231.1 ; v1(2609,2968) 2609,2972 2660,2972 2665.61,2966.39 U2.14 U2.18@2733.8,2966.39 ; v1(2684,3063) 2684,3059 2716,3059 2723.57,3051.43 U2.12@2723.57,3038 ; v1(2686,3028) U2.12@2723.57,3028 ; U2.12@2723.57,3022 U2.12 ; U2.9 2828,3028.2 ; v1@2837.35,3028.2 U2.8 2875,2991.59 v1(2875,2994) ; v1(3002,2519) 3033,2519 ; C121.2 3033,2519 ; C1301.2 3033,2519 ; U2.12 U2.12@2723.57,3038 ; U2.12 U2.12@2723.57,3038
  1 w20: P3.2@2351,3434.9 P3.2@2354,3431.9
  1 w23: P3.3@2347,3229.9 P3.3 2407,3229.9 v1(2407,3224.9) ; P3.2@2349,3431.9 P3.2@2351,3431.9 ; P3.2@2349,3439 P3.2@2351,3437 ; v1(2351,3376.9) P3.2@2351,3431.9 ; P3.2@2354,3431.9 P3.2@2352.9,3431.9 ; v1(2410,3431.9) P3.2@2352.9,3431.9 ; P3.5@2554,3429.1 v1(2607,3429.1) ; P3.2@2351,3431.9 P3.2@2352.9,3431.9
  1 w25: v1(2296,3432.9) P3.2@2348,3432.9 ; v1(2301,3225.9) P3.3@2347,3225.9 ; v1(2347,3282.9) 2347,3229.9 P3.3@2347,3225.9 ; P3.2@2349,3431.9 2349,3439 v1(2349,3490.9) ; v1(2352,3176.9) 2347,3176.9 P3.3@2347,3225.9 ; P3.5@2555,3426.9 2558,3429.9 v1(2558,3482.9) ; v1(2556,3176.9) 2556,3232.9 2611,3232.9 v1(2611,3225.1)
  4 w10: v1(2519,2720) 2530,2720
  4 w18: v1@2067,2691 P1.1 ; 3293,2093 v1(3309,2093)
  4 w20: v1(2065,2241) P1.19
  other v1: 2274,1949 2330,1951 2212,1957 3446,1959 2080,1962 3370,1963 2153,1966 2200,2007 3060,2007 2482,2013 2741,2013 2671,2015 3121,2015 3482,2015 2425,2024 2579,2024 2814,2025 2876,2026 2515,2029 3160,2034 2057,2038 2913,2043 2968,2045 3347,2059 3003,2062 2168,2066 3077,2074 2426,2077 2312,2081 3037,2081 2245,2082 2109,2087 2486,2087 2630,2087 2567,2088 2696,2088 2753,2088 2844,2089 3129,2089 2933,2090 2045,2094 3250,2103 3352,2118 3094,2144 3283,2145 3051,2147 2985,2155 2337,2165 2710,2165 2841,2167 2883,2168 2123,2169 2085,2172 2290,2183 2239,2184 2126,2198 3300,2200.95 2069,2204 3501,2204 3094,2245 3511,2251.95 2435,2269 3147,2282 2932,2283 3519,2297 2870,2300 2900,2315 2965,2315 3140,2322 3019,2327 2536,2382 2591,2385 3025,2405 3159,2405 2559,2412 2985,2445 2478,2457 3513,2499 2518,2529 2490,2557 2548,2563 2654,2567 3514,2573 2620,2582 2980,2585 2668,2598 2952,2605 2995,2610 2620,2611 2839,2631 2962,2633 3083,2633 2409,2635 2876,2638 3038,2640 2543,2641 3156,2657 2634,2665 3110,2670 2498,2673 3520,2675 3002,2677 2422,2679 2676,2679 3047,2682 2856,2690 2067,2692 2703,2692 3146,2698 3081,2702 2564,2703 2466,2721 3121,2723 2971,2724 2334,2730 3029,2742 3066,2742 3522,2745 2409,2749 2069,2750 3002,2750 2679.4,2756.4 3240,2757 2844,2758 2642.9,2758.6 2106,2761 2541,2761 2460,2763 3099,2763 3162,2763 2866,2770 2331,2777 2269,2782 2613,2782.6 2711.6,2782.6 2871.6,2800.4 2325,2801 2106,2811 3520,2812 3240,2828 2198,2829 2540,2835 2054,2836 2404,2837 2452,2838 3009,2838 2253,2842 2505,2848 2107,2850 3175,2850 3124,2852 2471,2863 2972,2870 2520,2872 2595,2875 3509,2875.95 2364,2879 3379,2881 3448,2881 2836.3,2881.8 3129,2892 2157,2893 2399,2893 3067,2894 3166,2895 2485,2904 3223,2904 2102,2910 2253,2912 3345,2912 2561,2924 3014,2939 2982,2943 2191,2951 2566,2951 3450,2950.95 3509,2950.95 2536,2956 3133,2958 3374,2965 2155,2966 3304,2967 3224,2968 2103,2969 2258,2969 3077,2972 2460,2981 2985,2981 2376,2992 2220,2999 2068.8,3000.7 2126.8,3012.7 2454.7,3013.7 3125,3016 2836.1,3019.4 2881,3023 3011,3023 3375,3025.95 3450,3025.95 3509,3025.95 2330,3030 2257,3033 2168.6,3034.5 2422,3035 3150,3035 2602,3036 2472,3041 3301,3041 3227,3042 2827.6,3043.9 2936,3045 2500.3,3050.4 2226,3055 2979,3055 3024,3055 2561,3063 2533,3064 3475,3072 3400,3075 2175.8,3083.3 3059,3085 2379,3091 3282,3092 3169,3093 2978,3096 3023,3097 2434,3110 2325,3111 2213.1,3114.2 3509,3115 2692.5,3117.3 3452,3118 2873,3119 3001,3120 3226,3123 2268.1,3131.2 2923,3132 2397,3137 2527,3139 3267,3139 3337,3139 2596,3145 3079,3149 2680.1,3150.5 3150,3150 2460,3151 3400,3151 2802.7,3156 2873,3156.7 2980,3157 3025,3157 2928,3159 3225,3175.95 3509,3175.95 2269.1,3179.2 2177.1,3182.2 2131,3183 2911,3185 2944,3185 2693.1,3187.5 3459,3191 2052,3192 2841,3196 2979,3198 3024,3199 2209.1,3205.2 2891,3214 3337,3216 3273,3218 2047,3224 3000,3225 3075,3225 3150,3225 3225,3225 3509,3225 2811,3227 2492,3228 2923,3254 2121,3258 2833,3258 2265,3260 2207,3287 2833,3291 3000,3300 3075,3300 3150,3300 3225,3300 3300,3300 3509,3300 2054,3301 2951,3319 2830,3322 2128,3324 2257,3325 2795.9,3330.2 3135,3340 3188,3340 3378,3343 3475,3348 3233,3352 2208,3362 2052,3364 3320,3366 3467,3385 2272,3386 3028,3387 3124,3387 2951,3393 3262,3393 3397,3393 3083,3394 3181,3397 2131,3402 2869,3404 3325,3426 3223,3429 2665,3432 3038,3436 3277,3436 2253,3438 2052,3439 3478,3444 2857,3445 3108,3447 2910,3452 3396,3465 2143,3470 2665,3478 3346,3479 2969,3487 3482,3487 3054,3489 3438,3492 2062,3493 2853,3495 3260,3514 2657,3541 2843,3543 3393,3549 3480,3550 2275,3553 2079,3554 2131,3556 2942,3557 2201,3559 2531,3563 3352,3563 3274,3565 2435,3566 2482,3566 2999,3566 2613,3570 2700,3570 3103,3570 2868,3572 3210,3573 2814,3574 2339,3578 2575,3579
VDD: L2.2 P2.7 P2.9 R8.1 | length 367.3
  1 w18: v1(3267,2540) 3267,2653 3284,2670 R8.1
  1 w20: v1(3267,2540) 3283.65,2523.35 L2.2
  4 w20: v1(3267,2540) P2.7@3325,2540 ; P2.9 P2.7@3325,2540 ; P2.7 P2.7@3325,2540
VDD2: P2.1 P2.3 P2.5 R8.3 | length 192.5
  1 w8: v1(3325,2724) 3325,2753.15 R8.3
  1 w20: v1(3325,2724) 3325.6,2724 R8.3
  4 w20: P2.5 P2.3 P2.1 v1(3325,2724)
VDD_CC2520: C2.1 C1401.1 C1501.1 C1601.1 L2.1 R261.2 U1.8 U1.11 U1.14 U1.15 U1.16 U1.20 U1.21 U1.22 U1.24 | length 3386
  1 w8: R261.2 2480,2276 v1(2481,2276) ; U1.14 2885.24,2517.24 2904,2536 2904,2565.65 C1501.1@2904.35,2566
  1 w10: 2651,2530 2663.76,2517.24 U1.22 ; U1.14 2885.24,2517.24 2904,2536 2904,2558 C1501.1@2903.31,2558
  1 w12: v1(2576,2559) 2591.65,2543.35 C1601.1 C1601.1@2591.65,2530 ; U1.20 U1.21 2680.57,2558.57 2652,2530 2651,2530 C1601.1@2591.65,2530 ; U1.15 U1.16 2813.37,2558 C1501.1@2903.31,2558 ; U1.8 2875.57,2398.43 2913.35,2360.65 C1401.1 2965,2360.65 ; U1.11 2920.82,2458.18 2965,2414 2965,2360.65 ; C1501.1 2904.35,2566 2904.35,2590 v1(2905,2590) ; v1@2993,2360.65 2965,2360.65 ; C1601.1@2591.65,2530 2591.65,2495 2593.87,2495 2611,2477.87 2656,2477.87 ; 2656,2477.87 U1.24 2656,2477.87
  1 w20: v1@2993,2360.65 v1(2993,2362) ; v1(3200,2429) C2.1 3240.35,2429 3240.35,2448 ; 3240.35,2448 L2.1 3240.35,2448
  3 w12: v1(2481,2276) 2565,2276 2611,2322 2779,2322 2865,2236 3027,2236 3107,2316 3107,2365 ; v1(2576,2559) 2576,2497 2578,2495 2578,2482 2579,2482 2715,2346 2788,2346 2875,2259 3001,2259 3107,2365 ; v1(2905,2590) 2905,2500 2919,2486 2999,2486 3107,2378 3107,2365 ; v1(2993,2362) 2993,2359.95 3105.95,2359.95 3107,2361 3107,2365 ; v1(3200,2429) 3200,2507 3239,2507 3238,2508 3188,2508 3107,2427 3107,2365
VDD_CC2591: C1.1 C11.1 C12.1 C131.1 C132.1 C161.1 L1.1 L102.1 U2.1 U2.13 U2.16 | length 610.6
  1 w8: v1(2502,2992) 2509,2992 2509,2991.7 C132.1 ; C131.1 C132.1 ; v1(2642,2876) 2641.8,2876 C161.1 2641.8,2915.21 U2.16 ; U2.13 2532.28,2991.98 C132.1 ; L102.1 2910,3075.75 v1(2910,3076)
  1 w14: U2.1 2723.96,2855.96 2699.6,2831.6 C11.1 C12.1@2647,2831.6 ; C12.1@2647,2831.6 C12.1 2614,2831.6 2608,2831.6 v1(2608,2832) 2646.6,2832 C12.1@2647,2831.6
  1 w18: C1.1 C1.1@3284,2874 ; L1.1 C1.1@3284,2874 ; v1(3284,2922) C1.1@3284,2874
pads on no net: FM1.1 FM2.1 FM3.1 FM4.1 FM5.1 FM6.1 P1.2 P1.4 P1.5 P1.6 P1.8 P1.15 P1.17 P1.21 P1.22 P2.2 P2.4 P2.6 P2.8 P2.10 P2.11 P2.12 P2.13 P2.14 P2.16 P2.20 P2.21 P2.22 U1.18 U2.3 X1.2 X1.4

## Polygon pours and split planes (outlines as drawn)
AGND on 1 "AGND_L1_2" (solid, remove dead copper, pour order 1001): 2249,2927 3546,2922.36 3546,1918 2004,1918 2003,2927
AGND on 1 "AGND_L1_1" (solid, remove dead copper, pour order 1000): 2004,3599 3546,3599 3546,2802 2001,2802
VDD_CC2520 on 3 "VDD_CC2520_L3_2" (solid, remove dead copper, pour order 1003): 2007,2768 3549,2768 3549,1919 2007,1919
VDD_CC2591 on 3 "VDD_CC2590_L3_1" (solid, remove dead copper, pour order 1002): 2007,3599 3549,3599 3549,2804 2007,2804
AGND on 4 "AGND_L4_6" (solid, remove dead copper, pour order 1009): 2004,1918 2574,1918 2574,2864.54 2245,2864.54 2003,2866
AGND on 4 "AGND_L4_4" (solid, remove dead copper, pour order 1008): 2528,1918 3016,1918 3016,2866 2528,2866
AGND on 4 "AGND_L4_5" (solid, remove dead copper, pour order 1007): 2969,1918 3542,1918 3542,2864 2969,2864
AGND on 4 "AGND_L4_1" (solid, remove dead copper, pour order 1006): 2002,2801 2573,2801 2573,3599 2003,3599
AGND on 4 "AGND_L4_3" (solid, remove dead copper, pour order 1005): 2968,2801 3541,2801 3541,3599 2968,3599
AGND on 4 "AGND_L4_2" (solid, remove dead copper, pour order 1004): 2527,2799 3015,2799 3015,3599 2527,3599
AGND on AGND "AGND_L2_2" (solid, remove dead copper, pour order 1011): 2004,2864 3547,2864 3546,1918 2004,1918
AGND on AGND "AGND_L2_1" (solid, remove dead copper, pour order 1010): 2004,3599 3546,3599 3546,2801 2002,2801

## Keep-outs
Keep-Out Layer:
  the board outline again, w1

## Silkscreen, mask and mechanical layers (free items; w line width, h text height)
Top Silk:
  text "Texas Instruments" at 2857,3494.6 h24.5
  text "CC2520-CC2591EM 3.0" at 2861,3447.7 h24.5
Top Solder Resist:
  region: 3219.02,2819 3219.02,2780 2871,2780 2871,2819
  region: 3219.02,1992.01 3179.65,1992.01 3179.65,2779.41 3219.02,2779.41
  region: 3219,1992 3219,1952.63 2352.86,1952.63 2352.86,1992
  region: 2352.87,2780 2392.24,2780 2392.24,1992.6 2352.87,1992.6
  region: 2626,2820 2626,2780.63 2352.86,2780.63 2352.86,2820

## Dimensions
2021,3893 to 2021,1917 on Unassigned
2003,2087 to 3549,2087 on Unassigned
